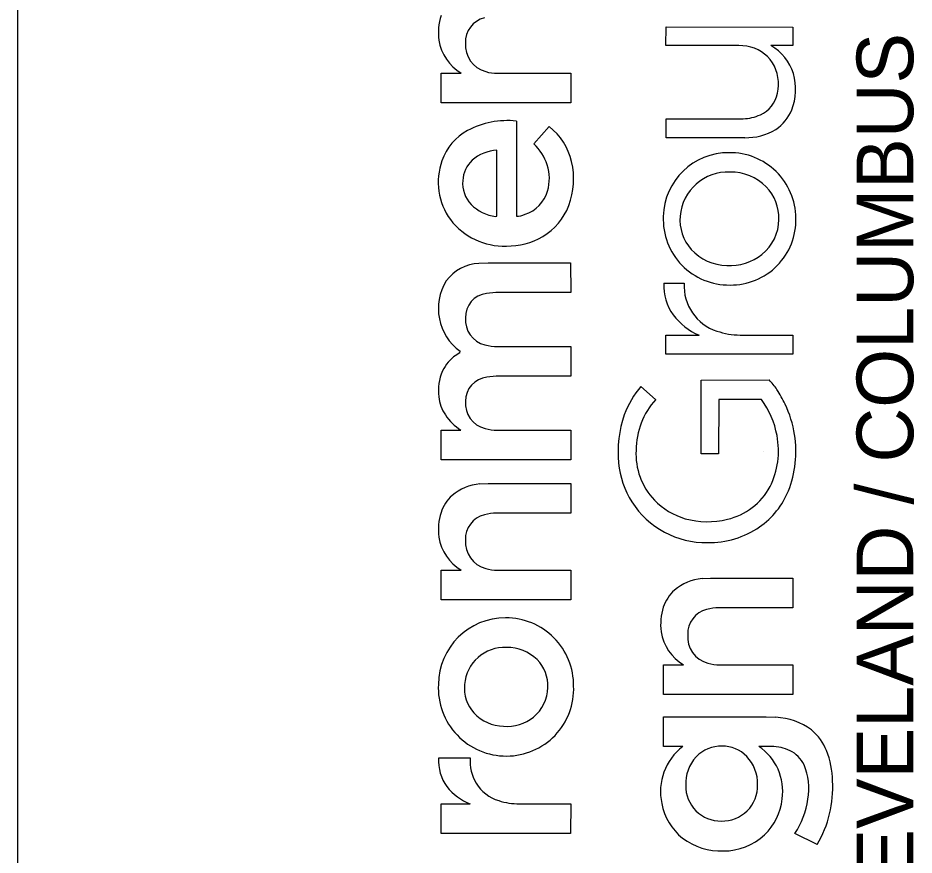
# Model space of a CAD drawing. Extents: x -31.8 to 34, y 0 to 22.
# Drawn here: x 32 to 32.901, y 3.094 to 3.936 of the extents above; entities that cross this region are included whole.
import ezdxf

# ---------------------------------------------------------------- set-up
doc = ezdxf.new("R2010")
doc.units = 0
doc.layers.add('_CIVIL_CONSTRUCTION', color=7, linetype='Continuous')
doc.layers.add('PF_X_Ground_Line', color=7, linetype='Continuous')

msp = doc.modelspace()

# ---------------------------------------------------------------- linework, layer by layer
at = {"layer": '_CIVIL_CONSTRUCTION'}
for p, q in [((32.65152, 3.90801), (32.65153, 3.92672)), ((32.65153, 3.92672), (32.7791, 3.92664)), ((32.7791, 3.92664), (32.77908, 3.90796)), ((32.7249, 3.90796), (32.65152, 3.90801)), ((32.7328, 3.90727), (32.7249, 3.90796)), ((32.77908, 3.90796), (32.75689, 3.90796)), ((32.42542, 3.88016), (32.44552, 3.88021)), ((32.42542, 3.85035), (32.42542, 3.88016)), ((32.48222, 3.88021), (32.55569, 3.88021)), ((32.55569, 3.88021), (32.55571, 3.85045)), ((32.55571, 3.85045), (32.42542, 3.85035)), ((32.50108, 3.83209), (32.50118, 3.73657)), ((32.65154, 3.83443), (32.72905, 3.8345)), ((32.65165, 3.81543), (32.65154, 3.83443)), ((32.51882, 3.80927), (32.53422, 3.82662)), ((32.73073, 3.81543), (32.65165, 3.81543)), ((32.48144, 3.73644), (32.48144, 3.80296)), ((32.48016, 3.73628), (32.48144, 3.73644)), ((32.46329, 3.68915), (32.47259, 3.68968)), ((32.47259, 3.68968), (32.55557, 3.68968)), ((32.55557, 3.68968), (32.55571, 3.65982)), ((32.64932, 3.66907), (32.66978, 3.66907)), ((32.48058, 3.65981), (32.47102, 3.65881)), ((32.55571, 3.65982), (32.48058, 3.65981)), ((32.65152, 3.61699), (32.68476, 3.617)), ((32.65152, 3.598), (32.65152, 3.61699)), ((32.72605, 3.61703), (32.7791, 3.61696)), ((32.7791, 3.61696), (32.77903, 3.598)), ((32.48218, 3.60553), (32.55571, 3.60548)), ((32.55571, 3.60548), (32.55571, 3.57568)), ((32.44443, 3.59922), (32.44455, 3.60072)), ((32.77903, 3.598), (32.65152, 3.598)), ((32.4809, 3.57567), (32.47143, 3.57474)), ((32.55571, 3.57568), (32.4809, 3.57567)), ((32.6868, 3.57185), (32.75516, 3.57192)), ((32.6868, 3.49778), (32.6868, 3.57185)), ((32.62636, 3.56548), (32.64114, 3.55241)), ((32.70448, 3.55241), (32.70432, 3.49775)), ((32.74737, 3.55227), (32.70448, 3.55241)), ((32.42542, 3.49152), (32.42545, 3.52138)), ((32.42545, 3.52138), (32.44515, 3.52138)), ((32.48206, 3.52138), (32.55571, 3.52136)), ((32.55571, 3.52136), (32.55571, 3.49156)), ((32.70432, 3.49775), (32.6868, 3.49778)), ((32.75, 3.5), (32.75, 3.5)), ((32.55571, 3.49156), (32.42542, 3.49152)), ((32.46439, 3.46736), (32.47289, 3.46783)), ((32.47289, 3.46783), (32.55571, 3.46783)), ((32.55571, 3.46783), (32.55571, 3.43804)), ((32.55571, 3.43804), (32.4814, 3.43796)), ((32.42542, 3.38066), (32.44552, 3.38071)), ((32.42542, 3.35086), (32.42542, 3.38066)), ((32.48222, 3.38071), (32.55569, 3.38071)), ((32.55569, 3.38071), (32.55571, 3.35096)), ((32.68784, 3.3722), (32.69634, 3.37266)), ((32.69634, 3.37266), (32.77916, 3.37266)), ((32.77916, 3.37266), (32.77917, 3.34287)), ((32.55571, 3.35096), (32.42542, 3.35086)), ((32.77917, 3.34287), (32.70485, 3.3428)), ((32.64888, 3.2855), (32.66897, 3.28555)), ((32.64888, 3.25569), (32.64888, 3.2855)), ((32.70568, 3.28555), (32.77915, 3.28555)), ((32.77915, 3.28555), (32.77917, 3.25579)), ((32.77917, 3.25579), (32.64888, 3.25569)), ((32.6489, 3.20336), (32.64889, 3.23322)), ((32.64889, 3.23322), (32.75236, 3.23322)), ((32.75236, 3.23322), (32.76191, 3.23285)), ((32.66836, 3.20336), (32.6489, 3.20336)), ((32.75763, 3.20356), (32.74487, 3.20361)), ((32.42299, 3.19193), (32.45454, 3.19193)), ((32.42542, 3.14577), (32.45473, 3.14579)), ((32.42542, 3.11593), (32.42542, 3.14577)), ((32.50413, 3.14581), (32.55571, 3.14573)), ((32.55571, 3.14573), (32.55565, 3.11593)), ((32.55565, 3.11593), (32.42542, 3.11593)), ((32.8036, 3.10491), (32.7812, 3.11598))]:
    msp.add_line(p, q, dxfattribs=at)
for points in [[(32.7328, 3.90727), (32.7249, 3.90796), (32.65152, 3.90801), (32.65153, 3.92672), (32.7791, 3.92664), (32.77908, 3.90796), (32.75689, 3.90796)], [(32.42542, 3.85035), (32.42542, 3.88016), (32.44552, 3.88021)], [(32.48222, 3.88021), (32.55569, 3.88021), (32.55571, 3.85045), (32.42542, 3.85035)], [(32.50108, 3.83209), (32.50118, 3.73657)], [(32.73073, 3.81543), (32.65165, 3.81543), (32.65154, 3.83443), (32.72905, 3.8345)], [(32.51882, 3.80927), (32.53422, 3.82662)], [(32.48016, 3.73628), (32.48144, 3.73644), (32.48144, 3.80296)], [(32.46329, 3.68915), (32.47259, 3.68968), (32.55557, 3.68968), (32.55571, 3.65982), (32.48058, 3.65981), (32.47102, 3.65881)], [(32.64932, 3.66907), (32.66978, 3.66907)], [(32.72605, 3.61703), (32.7791, 3.61696), (32.77903, 3.598), (32.65152, 3.598)], [(32.65152, 3.598), (32.65152, 3.61699), (32.68476, 3.617)], [(32.48218, 3.60553), (32.55571, 3.60548), (32.55571, 3.57568), (32.4809, 3.57567), (32.47143, 3.57474)], [(32.44443, 3.59922), (32.44455, 3.60072)], [(32.74737, 3.55227), (32.70448, 3.55241), (32.70432, 3.49775), (32.6868, 3.49778), (32.6868, 3.57185), (32.75516, 3.57192)], [(32.62636, 3.56548), (32.64114, 3.55241)], [(32.42542, 3.49152), (32.42545, 3.52138), (32.44515, 3.52138)], [(32.48206, 3.52138), (32.55571, 3.52136), (32.55571, 3.49156), (32.42542, 3.49152)], [(32.46439, 3.46736), (32.47289, 3.46783), (32.55571, 3.46783), (32.55571, 3.43804), (32.4814, 3.43796)], [(32.42542, 3.35086), (32.42542, 3.38066), (32.44552, 3.38071)], [(32.48222, 3.38071), (32.55569, 3.38071), (32.55571, 3.35096), (32.42542, 3.35086)], [(32.68784, 3.3722), (32.69634, 3.37266), (32.77916, 3.37266), (32.77917, 3.34287), (32.70485, 3.3428)], [(32.64888, 3.25569), (32.64888, 3.2855), (32.66897, 3.28555)], [(32.70568, 3.28555), (32.77915, 3.28555), (32.77917, 3.25579), (32.64888, 3.25569)], [(32.66836, 3.20336), (32.6489, 3.20336), (32.64889, 3.23322), (32.75236, 3.23322), (32.76191, 3.23285)], [(32.75763, 3.20356), (32.74487, 3.20361)], [(32.42299, 3.19193), (32.45454, 3.19193)], [(32.50413, 3.14581), (32.55571, 3.14573), (32.55565, 3.11593), (32.42542, 3.11593)], [(32.42542, 3.11593), (32.42542, 3.14577), (32.45473, 3.14579)], [(32.8036, 3.10491), (32.7812, 3.11598)]]:
    msp.add_lwpolyline(points, dxfattribs=at)
for centre, radius, start, end in [((32.47872, 3.92108), 0.05602, 162.27398, 187.79173), ((32.47872, 3.92108), 0.05602, 162.27398, 187.79173), ((32.47482, 3.91155), 0.02498, 103.68683, 182.21395), ((32.47482, 3.91155), 0.02498, 103.68683, 182.21395), ((32.47027, 3.9209), 0.04763, 188.96462, 238.69865), ((32.47027, 3.9209), 0.04763, 188.96462, 238.69865), ((32.47735, 3.90846), 0.02757, 175.58441, 255.13816), ((32.47735, 3.90846), 0.02757, 175.58441, 255.13816), ((32.72711, 3.86998), 0.03772, 33.50082, 81.32954), ((32.72711, 3.86998), 0.03772, 33.50082, 81.32954), ((32.73239, 3.86485), 0.04959, 17.62209, 60.38974), ((32.73239, 3.86485), 0.04959, 17.62209, 60.38974), ((32.72414, 3.8695), 0.04048, 346.56179, 31.75389), ((32.72414, 3.8695), 0.04048, 346.56179, 31.75389), ((32.48183, 3.92235), 0.04215, 254.08913, 270.52838), ((32.48183, 3.92235), 0.04215, 254.08913, 270.52838), ((32.72343, 3.86415), 0.05838, 339.16197, 15.61485), ((32.72343, 3.86415), 0.05838, 339.16197, 15.61485), ((32.73371, 3.86616), 0.03042, 294.63214, 348.48625), ((32.73371, 3.86616), 0.03042, 294.63214, 348.48625), ((32.72747, 3.88081), 0.04633, 271.95199, 294.08943), ((32.72747, 3.88081), 0.04633, 271.95199, 294.08943), ((32.739, 3.85901), 0.04201, 303.10391, 338.15613), ((32.739, 3.85901), 0.04201, 303.10391, 338.15613), ((32.49176, 3.74874), 0.08387, 83.62118, 118.28448), ((32.49176, 3.74874), 0.08387, 83.62118, 118.28448), ((32.47894, 3.77368), 0.05583, 118.82935, 160.62242), ((32.47894, 3.77368), 0.05583, 118.82935, 160.62242), ((32.49399, 3.7763), 0.06443, 13.53275, 51.36266), ((32.49399, 3.7763), 0.06443, 13.53275, 51.36266), ((32.7321, 3.87256), 0.05715, 268.62699, 301.47779), ((32.7321, 3.87256), 0.05715, 268.62699, 301.47779), ((32.4844, 3.76071), 0.04236, 94.01311, 130.88062), ((32.4844, 3.76071), 0.04236, 94.01311, 130.88062), ((32.48033, 3.77018), 0.05485, 19.0387, 45.44322), ((32.48033, 3.77018), 0.05485, 19.0387, 45.44322), ((32.71435, 3.73484), 0.06552, 89.48213, 178.77752), ((32.71435, 3.73484), 0.06552, 89.48213, 178.77752), ((32.71582, 3.73414), 0.06623, 0.42265, 90.7613), ((32.71582, 3.73414), 0.06623, 0.42265, 90.7613), ((32.48697, 3.77074), 0.06438, 160.52138, 215.78155), ((32.48697, 3.77074), 0.06438, 160.52138, 215.78155), ((32.47703, 3.7709), 0.02985, 132.98553, 177.1802), ((32.47703, 3.7709), 0.02985, 132.98553, 177.1802), ((32.48724, 3.77433), 0.04701, 344.60723, 17.00675), ((32.48724, 3.77433), 0.04701, 344.60723, 17.00675), ((32.48289, 3.77384), 0.0758, 339.35431, 13.37708), ((32.48289, 3.77384), 0.0758, 339.35431, 13.37708), ((32.71397, 3.73244), 0.04846, 87.68827, 175.01696), ((32.71397, 3.73244), 0.04846, 87.68827, 175.01696), ((32.71659, 3.73036), 0.05052, 44.91202, 90.75914), ((32.71659, 3.73036), 0.05052, 44.91202, 90.75914), ((32.47824, 3.76966), 0.03114, 175.00138, 223.2876), ((32.47824, 3.76966), 0.03114, 175.00138, 223.2876), ((32.71955, 3.73452), 0.04549, 358.32279, 43.83486), ((32.71955, 3.73452), 0.04549, 358.32279, 43.83486), ((32.49895, 3.77177), 0.03504, 288.01084, 343.55364), ((32.49895, 3.77177), 0.03504, 288.01084, 343.55364), ((32.48546, 3.77826), 0.04232, 225.06454, 262.79701), ((32.48546, 3.77826), 0.04232, 225.06454, 262.79701), ((32.49548, 3.76982), 0.0626, 300.94393, 338.73223), ((32.49548, 3.76982), 0.0626, 300.94393, 338.73223), ((32.48908, 3.77516), 0.06872, 217.74341, 271.65606), ((32.48908, 3.77516), 0.06872, 217.74341, 271.65606), ((32.50129, 3.75678), 0.02021, 269.70042, 294.87295), ((32.50129, 3.75678), 0.02021, 269.70042, 294.87295), ((32.71483, 3.7334), 0.06606, 177.53728, 270.94524), ((32.71483, 3.7334), 0.06606, 177.53728, 270.94524), ((32.71085, 3.73311), 0.0453, 175.51467, 221.42047), ((32.71085, 3.73311), 0.0453, 175.51467, 221.42047), ((32.71671, 3.73271), 0.06536, 269.30834, 1.67905), ((32.71671, 3.73271), 0.06536, 269.30834, 1.67905), ((32.71931, 3.73374), 0.04572, 308.90382, 359.30947), ((32.71931, 3.73374), 0.04572, 308.90382, 359.30947), ((32.49204, 3.77702), 0.07055, 269.20529, 300.33566), ((32.49204, 3.77702), 0.07055, 269.20529, 300.33566), ((32.71399, 3.73734), 0.05046, 222.66255, 268.37331), ((32.71399, 3.73734), 0.05046, 222.66255, 268.37331), ((32.71567, 3.73859), 0.05178, 266.55312, 308.67253), ((32.71567, 3.73859), 0.05178, 266.55312, 308.67253), ((32.46638, 3.64404), 0.04521, 93.91118, 142.30723), ((32.46638, 3.64404), 0.04521, 93.91118, 142.30723), ((32.47585, 3.64373), 0.05319, 148.28793, 233.9556), ((32.47585, 3.64373), 0.05319, 148.28793, 233.9556), ((32.69878, 3.66662), 0.04952, 177.16211, 216.28024), ((32.69878, 3.66662), 0.04952, 177.16211, 216.28024), ((32.71735, 3.66638), 0.04764, 176.76988, 252.15044), ((32.71735, 3.66638), 0.04764, 176.76988, 252.15044), ((32.47384, 3.63499), 0.02399, 96.75763, 181.6251), ((32.47384, 3.63499), 0.02399, 96.75763, 181.6251), ((32.47577, 3.63241), 0.02597, 175.81573, 256.16716), ((32.47577, 3.63241), 0.02597, 175.81573, 256.16716), ((32.70975, 3.67555), 0.06366, 216.91526, 246.88619), ((32.70975, 3.67555), 0.06366, 216.91526, 246.88619), ((32.7269, 3.69175), 0.07473, 251.13884, 269.34694), ((32.7269, 3.69175), 0.07473, 251.13884, 269.34694), ((32.4817, 3.65053), 0.04501, 254.34629, 270.61033), ((32.4817, 3.65053), 0.04501, 254.34629, 270.61033), ((32.4638, 3.56267), 0.04137, 117.91625, 139.24296), ((32.4638, 3.56267), 0.04137, 117.91625, 139.24296), ((32.46194, 3.56452), 0.03875, 139.52447, 154.84698), ((32.46194, 3.56452), 0.03875, 139.52447, 154.84698), ((32.47144, 3.5612), 0.04877, 156.06382, 187.3493), ((32.47144, 3.5612), 0.04877, 156.06382, 187.3493), ((32.47421, 3.55056), 0.02434, 96.5532, 179.94902), ((32.47421, 3.55056), 0.02434, 96.5532, 179.94902), ((32.72498, 3.53937), 0.04438, 30.98913, 47.16099), ((32.72498, 3.53937), 0.04438, 30.98913, 47.16099), ((32.70163, 3.50187), 0.09855, 139.79476, 159.13696), ((32.70163, 3.50187), 0.09855, 139.79476, 159.13696), ((32.67091, 3.50018), 0.11106, 25.30315, 33.96179), ((32.67091, 3.50018), 0.11106, 25.30315, 33.96179), ((32.46461, 3.55974), 0.04181, 186.5579, 213.38846), ((32.46461, 3.55974), 0.04181, 186.5579, 213.38846), ((32.47608, 3.54863), 0.02628, 175.722, 255.78627), ((32.47608, 3.54863), 0.02628, 175.722, 255.78627), ((32.69899, 3.50079), 0.07753, 138.25804, 179.70064), ((32.69899, 3.50079), 0.07753, 138.25804, 179.70064), ((32.67889, 3.50099), 0.08556, 10.07509, 36.83189), ((32.67889, 3.50099), 0.08556, 10.07509, 36.83189), ((32.6704, 3.49987), 0.11166, 8.80339, 25.33484), ((32.6704, 3.49987), 0.11166, 8.80339, 25.33484), ((32.47886, 3.57078), 0.0598, 214.70433, 235.68724), ((32.47886, 3.57078), 0.0598, 214.70433, 235.68724), ((32.7187, 3.49968), 0.11536, 161.14379, 185.62812), ((32.7187, 3.49968), 0.11536, 161.14379, 185.62812), ((32.48195, 3.56518), 0.0438, 253.66719, 270.14979), ((32.48195, 3.56518), 0.0438, 253.66719, 270.14979), ((32.68425, 3.50057), 0.08036, 333.46689, 11.03668), ((32.68425, 3.50057), 0.08036, 333.46689, 11.03668), ((32.67564, 3.49977), 0.10649, 338.28866, 9.28548), ((32.67564, 3.49977), 0.10649, 338.28866, 9.28548), ((32.68811, 3.49732), 0.06676, 176.66577, 223.6912), ((32.68811, 3.49732), 0.06676, 176.66577, 223.6912), ((32.69336, 3.49699), 0.08987, 185.50773, 212.01294), ((32.69336, 3.49699), 0.08987, 185.50773, 212.01294), ((32.46871, 3.41767), 0.04988, 94.97056, 130.22484), ((32.46871, 3.41767), 0.04988, 94.97056, 130.22484), ((32.69868, 3.49547), 0.0652, 282.88151, 331.81475), ((32.69868, 3.49547), 0.0652, 282.88151, 331.81475), ((32.69835, 3.49168), 0.08241, 305.03061, 337.67573), ((32.69835, 3.49168), 0.08241, 305.03061, 337.67573), ((32.46348, 3.42602), 0.04016, 132.22383, 161.68229), ((32.46348, 3.42602), 0.04016, 132.22383, 161.68229), ((32.69045, 3.50011), 0.07039, 224.02147, 253.88), ((32.69045, 3.50011), 0.07039, 224.02147, 253.88), ((32.69211, 3.49748), 0.08908, 212.70222, 270.71399), ((32.69211, 3.49748), 0.08908, 212.70222, 270.71399), ((32.47872, 3.42158), 0.05602, 162.27398, 187.79173), ((32.47872, 3.42158), 0.05602, 162.27398, 187.79173), ((32.47482, 3.41206), 0.02498, 103.68683, 182.21395), ((32.47482, 3.41206), 0.02498, 103.68683, 182.21395), ((32.48108, 3.39196), 0.04601, 89.60515, 105.33026), ((32.48108, 3.39196), 0.04601, 89.60515, 105.33026), ((32.69318, 3.51254), 0.08309, 254.45353, 283.9512), ((32.69318, 3.51254), 0.08309, 254.45353, 283.9512), ((32.69429, 3.49979), 0.09138, 269.3273, 304.19632), ((32.69429, 3.49979), 0.09138, 269.3273, 304.19632), ((32.47027, 3.42141), 0.04763, 188.96462, 238.69865), ((32.47027, 3.42141), 0.04763, 188.96462, 238.69865), ((32.47735, 3.40897), 0.02757, 175.58441, 255.13816), ((32.47735, 3.40897), 0.02757, 175.58441, 255.13816), ((32.48183, 3.42286), 0.04215, 254.08913, 270.52838), ((32.48183, 3.42286), 0.04215, 254.08913, 270.52838), ((32.69216, 3.32251), 0.04988, 94.97056, 130.22484), ((32.69216, 3.32251), 0.04988, 94.97056, 130.22484), ((32.68694, 3.33085), 0.04016, 132.22383, 161.68229), ((32.68694, 3.33085), 0.04016, 132.22383, 161.68229), ((32.70217, 3.32642), 0.05602, 162.27398, 187.79173), ((32.70217, 3.32642), 0.05602, 162.27398, 187.79173), ((32.70453, 3.29679), 0.04601, 89.60515, 105.33026), ((32.70453, 3.29679), 0.04601, 89.60515, 105.33026), ((32.69828, 3.31689), 0.02498, 103.68683, 182.21395), ((32.69828, 3.31689), 0.02498, 103.68683, 182.21395), ((32.49014, 3.26543), 0.0674, 89.84756, 179.64047), ((32.49014, 3.26543), 0.0674, 89.84756, 179.64047), ((32.49057, 3.26474), 0.0681, 359.54009, 90.21138), ((32.49057, 3.26474), 0.0681, 359.54009, 90.21138), ((32.69372, 3.32624), 0.04763, 188.96462, 238.69865), ((32.69372, 3.32624), 0.04763, 188.96462, 238.69865), ((32.7008, 3.31381), 0.02757, 175.58441, 255.13816), ((32.7008, 3.31381), 0.02757, 175.58441, 255.13816), ((32.48923, 3.26263), 0.0404, 87.04809, 175.57259), ((32.48923, 3.26263), 0.0404, 87.04809, 175.57259), ((32.49204, 3.25999), 0.04299, 45.84264, 90.98008), ((32.49204, 3.25999), 0.04299, 45.84264, 90.98008), ((32.49458, 3.26421), 0.03821, 357.88569, 44.15902), ((32.49458, 3.26421), 0.03821, 357.88569, 44.15902), ((32.70529, 3.32769), 0.04215, 254.08913, 270.52838), ((32.70529, 3.32769), 0.04215, 254.08913, 270.52838), ((32.49083, 3.26209), 0.06819, 176.8344, 270.40384), ((32.49083, 3.26209), 0.06819, 176.8344, 270.40384), ((32.48729, 3.2625), 0.03848, 175.15378, 221.14706), ((32.48729, 3.2625), 0.03848, 175.15378, 221.14706), ((32.49123, 3.26139), 0.06749, 270.06243, 2.37759), ((32.49123, 3.26139), 0.06749, 270.06243, 2.37759), ((32.49446, 3.26318), 0.0383, 308.28936, 359.43468), ((32.49446, 3.26318), 0.0383, 308.28936, 359.43468), ((32.48919, 3.26607), 0.04228, 223.09994, 268.80895), ((32.48919, 3.26607), 0.04228, 223.09994, 268.80895), ((32.49096, 3.2679), 0.04418, 266.56515, 308.06078), ((32.49096, 3.2679), 0.04418, 266.56515, 308.06078), ((32.75907, 3.16789), 0.06503, 53.40344, 87.49062), ((32.75907, 3.16789), 0.06503, 53.40344, 87.49062), ((32.76517, 3.18039), 0.05141, 21.60748, 50.5577), ((32.76517, 3.18039), 0.05141, 21.60748, 50.5577), ((32.70292, 3.15813), 0.05692, 127.37482, 192.22468), ((32.70292, 3.15813), 0.05692, 127.37482, 192.22468), ((32.70693, 3.16927), 0.0346, 88.47302, 136.42562), ((32.70693, 3.16927), 0.0346, 88.47302, 136.42562), ((32.70814, 3.16963), 0.03424, 44.27195, 90.47623), ((32.70814, 3.16963), 0.03424, 44.27195, 90.47623), ((32.71421, 3.15829), 0.05472, 352.1125, 55.92295), ((32.71421, 3.15829), 0.05472, 352.1125, 55.92295), ((32.75666, 3.15725), 0.04633, 65.01687, 88.8011), ((32.75666, 3.15725), 0.04633, 65.01687, 88.8011), ((32.7626, 3.17155), 0.03085, 26.26808, 63.80301), ((32.7626, 3.17155), 0.03085, 26.26808, 63.80301), ((32.73069, 3.16714), 0.08835, 1.15143, 21.3627), ((32.73069, 3.16714), 0.08835, 1.15143, 21.3627), ((32.46616, 3.18882), 0.04329, 175.87313, 216.34747), ((32.46616, 3.18882), 0.04329, 175.87313, 216.34747), ((32.50087, 3.18948), 0.04639, 176.9688, 209.60636), ((32.50087, 3.18948), 0.04639, 176.9688, 209.60636), ((32.71141, 3.16602), 0.0401, 137.46739, 182.33237), ((32.71141, 3.16602), 0.0401, 137.46739, 182.33237), ((32.70368, 3.166), 0.03996, 358.57141, 43.53765), ((32.70368, 3.166), 0.03996, 358.57141, 43.53765), ((32.73565, 3.16154), 0.05953, 349.30734, 23.43071), ((32.73565, 3.16154), 0.05953, 349.30734, 23.43071), ((32.47466, 3.19716), 0.05511, 218.09809, 248.7907), ((32.47466, 3.19716), 0.05511, 218.09809, 248.7907), ((32.49514, 3.18814), 0.04079, 211.94466, 253.2028), ((32.49514, 3.18814), 0.04079, 211.94466, 253.2028), ((32.70645, 3.1637), 0.03511, 178.88208, 271.08374), ((32.70645, 3.1637), 0.03511, 178.88208, 271.08374), ((32.70818, 3.16404), 0.03546, 268.27882, 1.55016), ((32.70818, 3.16404), 0.03546, 268.27882, 1.55016), ((32.70538, 3.16244), 0.11383, 329.6388, 3.25998), ((32.70538, 3.16244), 0.11383, 329.6388, 3.25998), ((32.50465, 3.2165), 0.07069, 252.46555, 269.57296), ((32.50465, 3.2165), 0.07069, 252.46555, 269.57296), ((32.70463, 3.15696), 0.05837, 190.75182, 231.28919), ((32.70463, 3.15696), 0.05837, 190.75182, 231.28919), ((32.70988, 3.15708), 0.05887, 313.74196, 353.8554), ((32.70988, 3.15708), 0.05887, 313.74196, 353.8554), ((32.70738, 3.16334), 0.08771, 327.31495, 351.57478), ((32.70738, 3.16334), 0.08771, 327.31495, 351.57478), ((32.70632, 3.16112), 0.06269, 232.46061, 272.59022), ((32.70632, 3.16112), 0.06269, 232.46061, 272.59022), ((32.70954, 3.15901), 0.06051, 269.6361, 312.70877), ((32.70954, 3.15901), 0.06051, 269.6361, 312.70877)]:
    msp.add_arc(centre, radius, start, end, dxfattribs=at)
at = {"layer": 'PF_X_Ground_Line'}
msp.add_line((32, 0.5), (32, 21.5), dxfattribs=at)

# ---------------------------------------------------------------- texts
at = {"layer": '_CIVIL_CONSTRUCTION'}
msp.add_text('AKRON / CLEVELAND / COLUMBUS', height=0.056969, rotation=90, dxfattribs=at).set_placement((32.90012, 2.638))

doc.saveas('drawing.dxf')
